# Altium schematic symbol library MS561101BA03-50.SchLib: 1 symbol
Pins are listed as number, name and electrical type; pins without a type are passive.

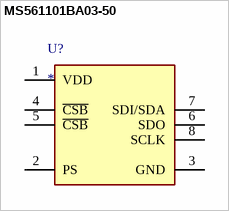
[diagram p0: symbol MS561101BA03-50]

## MS561101BA03-50
designator U?
Sensor;MS5611-BT M-CAPS 3X5X1MM T&R;Pressure;MS561101BA03-50 ¦ TE Connectivity MS561101BA03-50
footprint XDCR_MS561101BA03-50
pins: 1 VDD, 2 PS, 3 GND (power), 4 ~{CSB}, 5 ~{CSB}, 6 SDO, 7 SDI/SDA, 8 SCLK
